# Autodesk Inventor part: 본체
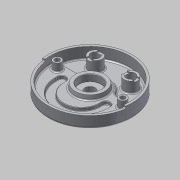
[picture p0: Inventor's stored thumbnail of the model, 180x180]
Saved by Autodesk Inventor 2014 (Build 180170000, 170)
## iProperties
Created: 2015-06
Part Number: 본체
Material: 알루미늄 6061
Document SubType Name: Modeling
Designer: MYHOME
Mass: 1070.79 g
Surface Area: 1034.57 cm^2
Volume: 395.125 cm^3
Density: 2.71 g/cm^3
Appearance: 알루미늄 - 평지
Author: MYHOME
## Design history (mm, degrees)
sketch "스케치7"
  geometry: C1 r 95 at (0, 0); 1 further point
  constraints: 1 centre point, 1 coincident
  dimensions: "d19" = 190 diameter of C1
extrude "돌출6" new body sketch "스케치7" distance "d20" = 32; taper "d21" = 0 deg
sketch "스케치8"
  geometry: C1 r 95 at (0, 0) reference; C2 r 90 at (0, 0)
  constraints: 1 centre point, 1 coincident
  dimensions: "d22" = 180 diameter of C2
extrude "돌출7" cut sketch "스케치8" distance "d23" = 18; taper "d24" = 0 deg
sketch "스케치9"
  geometry: L1 (38.833, 16)-(88.566, 16); L2 (-38.833, 16)-(-88.566, 16); A1 r 90 centre (0, 0) between (88.566, 16) and (-88.566, 16) reference; A2 r 42 centre (0, 0) between (38.833, 16) and (-38.833, 16)
  constraints: 4 end point, 4 point on circle, 1 centre point, 1 coincident, 1 collinear, 1 horizontal
  dimensions: "d25" = 42 radius of A2; "d26" = 16 distance from line of A1.centre L1; "d27" = 16 distance from line of A1.centre L2
extrude "돌출8" cut sketch "스케치9" distance "d28" = 7; taper "d29" = 0 deg
sketch "스케치10"
  geometry: C1 r 95 at (0, 0) reference; C2 r 26 at (0, 0)
  constraints: 1 centre point, 1 coincident
  dimensions: "d30" = 52 diameter of C2
extrude "돌출9" join sketch "스케치10" distance "d31" = 12; taper "d32" = -15 deg
sketch "스케치11"
  geometry: C1 r 22.785 at (0, 0) reference; C2 r 11.5 at (0, 0)
  constraints: 1 centre point, 1 coincident
  dimensions: "d33" = 23 diameter of C2
sketch "스케치12"
  geometry: C1 r 35 at (0, 0); A1 r 90 centre (0, 0) between (-88.566, 16) and (88.566, 16) reference
  constraints: 1 centre point, 1 coincident
  dimensions: "d34" = 70 diameter of C1
extrude "돌출10" join sketch "스케치12" distance "d35" = 10; taper "d36" = -10 deg
sketch "스케치13"
  geometry: C1 r 33.237 at (0, 0) reference; C2 r 25 at (0, 0)
  constraints: 1 centre point, 1 coincident
  dimensions: "d37" = 50 diameter of C2
extrude "돌출11" cut sketch "스케치13" distance "d38" = 15; taper "d39" = 0 deg
extrude "돌출12" cut sketch "스케치11" stored distance "d40" = 15; taper "d41" = 0 deg
sketch "스케치17"
  geometry: C1 r 15 at (-40, 52); C2 r 15 at (40, 52); A1 r 90 centre (0, 0) between (88.566, 16) and (-88.566, 16) reference
  constraints: 2 centre point
  dimensions: "d54" = 30 diameter of C1; "d55" = 30 diameter of C2; "d56" = 80 distance of C1.centre C2.centre; "d57" = 52 vertical distance of C2.centre A1.centre; "d59" = 52 vertical distance of A1.centre C1.centre; "d60" = 40 horizontal distance of A1.centre C2.centre
extrude "돌출16" join sketch "스케치17" distance "d61" = 25; taper "d62" = 0 deg
sketch "스케치18"
  geometry: L1 (-6, 17.367)-(6, 17.367); L2 (6, 17.367)-(6, -23.372); L3 (6, -23.372)-(-6, -23.372); L4 (-6, -23.372)-(-6, 17.367); C1 r 15 at (0, 0) reference; C2 r 15 at (80, 0) reference; 2 further points
  constraints: 8 end point, 2 parallel, 1 horizontal, 1 midpoint, 1 perpendicular, 1 vertical alignment
  dimensions: "d63" = 12 distance of L1.start L1.end
extrude "돌출17" cut sketch "스케치18" distance "d64" = 3; taper "d65" = 0 deg
sketch "스케치19"
  geometry: L1 (-19.836, 6)-(21.404, 6); L2 (21.404, 6)-(21.404, -6); L3 (21.404, -6)-(-19.836, -6); L4 (-19.836, -6)-(-19.836, 6); C1 r 15 at (0, 0) reference; 2 further points
  constraints: 8 end point, 2 parallel, 1 horizontal, 1 horizontal alignment, 1 midpoint, 1 perpendicular
  dimensions: "d66" = 12 distance of L1.end L2.end
extrude "돌출18" cut sketch "스케치19" distance "d67" = 3; taper "d68" = 0 deg
sketch "스케치20"
  geometry: L1 (-34, 65.748)-(-34, 38.252) reference; L2 (-46, 38.252)-(-46, 65.748) reference; L3 (-34, 65.748)-(-34, 38.252) reference; L4 (-46, 38.252)-(-46, 65.748) reference; L5 (53.748, 46)-(26.252, 46) reference; L6 (26.252, 58)-(53.748, 58) reference; L7 (53.748, 46)-(26.252, 46) reference; L8 (26.252, 58)-(53.748, 58) reference; C1 r 10 at (-40, 52); C2 r 10 at (40, 52); A1 r 15 centre (-40, 52) between (-34, 38.252) and (-34, 65.748) reference; A2 r 15 centre (-40, 52) between (-46, 65.748) and (-46, 38.252) reference; A3 r 15 centre (-40, 52) between (-46, 38.252) and (-34, 38.252) reference; A4 r 15 centre (-40, 52) between (-34, 65.748) and (-46, 65.748) reference; A5 r 15 centre (40, 52) between (26.252, 58) and (26.252, 46) reference; A6 r 15 centre (40, 52) between (53.748, 46) and (53.748, 58) reference; A7 r 15 centre (40, 52) between (26.252, 46) and (53.748, 46) reference; A8 r 15 centre (40, 52) between (53.748, 58) and (26.252, 58) reference
  constraints: 2 centre point, 2 coincident
  dimensions: "d69" = 20 diameter of C1; "d70" = 20 diameter of C2
extrude "돌출19" cut sketch "스케치20" stored distance "d71" = 3; taper "d72" = 0 deg
sketch "스케치21"
  geometry: L1 (-38.833, 16)-(-88.566, 16) reference; L2 (59, -19)-(59, -14); L3 (41, -19)-(41, -14); L4 (-41, -19)-(-41, -14); L5 (-59, -19)-(-59, -14); L6 (-59, -14)-(-41, -14); L7 (41, -14)-(59, -14); C1 r 35 at (0, 0) reference; A1 r 41 centre (0, -19) between (-41, -19) and (41, -19); A2 r 59 centre (0, -19) between (-59, -19) and (59, -19); A3 r 9 centre (-50, -14) between (-41, -14) and (-59, -14); A4 r 9 centre (50, -14) between (59, -14) and (41, -14)
  constraints: 12 end point, 8 point on circle, 4 centre point, 4 equal length, 4 horizontal alignment, 4 tangent, 2 midpoint, 2 perpendicular, 1 coincident, 1 vertical alignment
  dimensions: "d73" = 19 distance of A1.centre C1.centre; "d74" = 41 radius of A1; "d75" = 59 radius of A2; "d80" = 5 distance of L2.start L2.end; "d81" = 5 distance of L5.start L5.end
extrude "돌출20" cut sketch "스케치21" distance "d82" = 7; taper "d83" = 0 deg
sketch "스케치22"
  geometry: L1 (0, 0)-(94.075, -13.221); L2 (0, 0)-(110.218, 0); L3 (0, 0)-(-94.075, -13.221); L4 (0, 0)-(114.278, 0); A1 r 95 centre (0, 0) between (94.075, -13.221) and (-94.075, -13.221) reference; A2 r 90 centre (0, 0) between (-89.124, -12.526) and (89.124, -12.526); A3 r 95 centre (0, 0) between (-94.075, -13.221) and (94.075, -13.221); 1 further point
  constraints: 8 end point, 6 point on circle, 2 centre point, 2 coincident, 2 horizontal, 1 point on line, 2 other
  dimensions: "d84" = 8 deg angle of L1 L2; "d85" = 172 deg angle of L3 L4
extrude "돌출21" cut sketch "스케치22" distance "d86" = 5; taper "d87" = 0 deg
fillet "모깎기1" dims "d88" = 10
fillet "모깎기3" dims "d90" = 3
fillet "모깎기4" dims "d91" = 10
fillet "모깎기5" dims "d92" = 3
fillet "모깎기6" dims "d93" = 3
fillet "모깎기7" dims "d97" = 3
chamfer "모따기2" distance "d98" = 1; stored, may be unused: second distance "d99" = 2, angle "d100" = 45 deg
fillet "모깎기8" dims "d101" = 5
fillet "모깎기9" dims "d105" = 3
sketch "스케치23"
  geometry: C1 r 90 at (0, 0) reference; C2 r 68 at (0, 0)
  constraints: 1 centre point, 1 coincident, 1 other
  dimensions: "d107" = 136 diameter of C2
feature "엠보싱1" sketch "스케치23" dims "d19" = 190, "d108" = 0.5, "d109" = 0
chamfer "모따기4" distance "d110" = 1; stored, may be unused: second distance "d111" = 2, angle "d112" = 45 deg
fillet "모깎기10" dims "d113" = 0.3
sketch "스케치24"
  geometry: C1 r 90 at (0, 0) reference; C2 r 28.302 at (0, 0) reference; C3 r 9 at (74, 0); C4 r 9 at (-74, 0); A1 r 74 centre (0, 0) between (74, 0) and (-74, 0)
  constraints: 3 centre point, 2 horizontal alignment, 2 point on circle, 1 coincident
  dimensions: "d114" = 148 diameter of A1; "d115" = 18 diameter of C3; "d116" = 18 diameter of C4
extrude "돌출22" cut sketch "스케치24" distance "d117" = 11; taper "d118" = 0 deg
sketch "스케치25"
  geometry: C1 r 9 at (0, 0) reference; C2 r 9 at (148, 0) reference; C3 r 5.5 at (0, 0); C4 r 5.5 at (148, 0); 1 further point
  constraints: 2 centre point, 2 coincident
  dimensions: "d119" = 11 diameter of C3; "d120" = 11 diameter of C4
extrude "돌출23" cut sketch "스케치25" stored distance "d121" = 11; taper "d122" = 0 deg
sketch "스케치26"
  geometry: C1 r 5.5 at (74, 0) reference; C2 r 5.5 at (-74, 0) reference; C3 r 9 at (-74, 0); C4 r 9 at (74, 0)
  constraints: 2 centre point, 2 coincident
  dimensions: "d123" = 18 diameter of C3; "d124" = 18 diameter of C4
extrude "돌출24" join sketch "스케치26" distance "d125" = 18; taper "d126" = 0 deg
fillet "모깎기11" dims "d127" = 3
fillet "모깎기12" dims "d128" = 1
chamfer "모따기5" distance "d129" = 1; stored, may be unused: second distance "d130" = 2, angle "d131" = 45 deg
node "솔리드2"
node "투영된 루프2"
node "투영된 루프3"
node "투영된 루프4"
node "투영된 루프5"
node "투영된 루프6"
node "투영된 루프7"
node "투영된 루프8"
node "투영된 루프9"
other parameters: "d79" = 5
